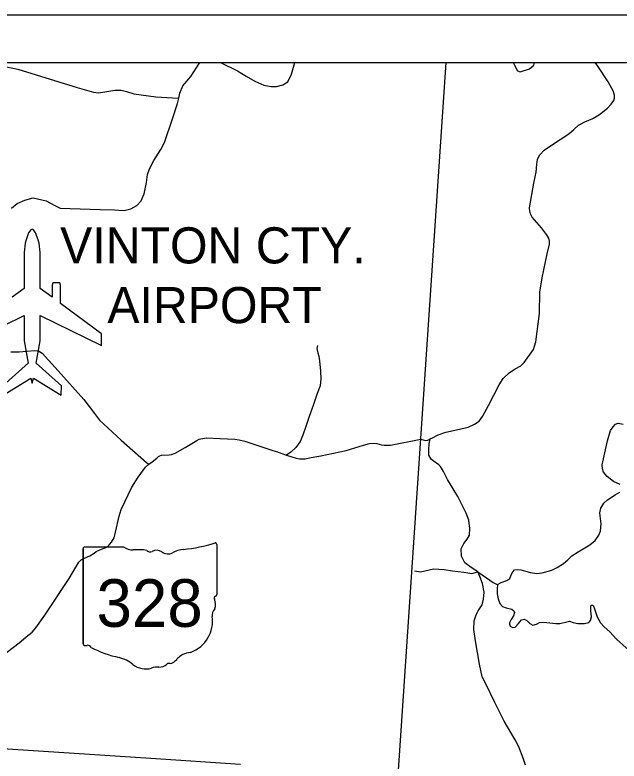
# Model space of a CAD drawing. Extents: x -22 to 431, y -18 to 160.
# Drawn here: x -17.504 to -16.235, y 27.599 to 29.164 of the extents above; entities that cross this region are included whole.
import ezdxf

# ---------------------------------------------------------------- set-up
doc = ezdxf.new("R2010")
doc.units = 0
for name, color, linetype in [('GM_X_Adjacent_County_Text', 7, 'Continuous'), ('GM_X_Airport_Location_Class_2', 7, 'Continuous'), ('GM_X_County_Road', 7, 'Continuous'), ('GM_X_County_ROW', 7, 'Continuous'), ('GM_X_Major_River_Text', 7, 'Continuous'), ('GM_X_Minor_River_Text', 7, 'Continuous'), ('GM_X_Section', 7, 'Continuous'), ('GM_X_Township_Text', 7, 'Continuous'), ('GM_X_US_Location', 7, 'Continuous')]:
    doc.layers.add(name, color=color, linetype=linetype)

msp = doc.modelspace()

# ---------------------------------------------------------------- linework, layer by layer
at = {"layer": 'GM_X_Adjacent_County_Text'}
for points in [[(-17.2858, 28.7545), (-17.2742, 28.7536), (-17.2602, 28.7571), (-17.2474, 28.7642), (-17.2388, 28.774), (-17.2321, 28.789), (-17.2277, 28.8126), (-17.2256, 28.8291), (-17.221, 28.8416), (-17.2117, 28.8586), (-17.1971, 28.8816), (-17.1899, 28.8968), (-17.1719, 28.9485), (-17.162, 28.9782), (-17.1596, 28.9898), (-17.1574, 29), (-17.1511, 29.0152), (-17.1346, 29.0351), (-17.1214, 29.0543), (-17.1155, 29.0642)], [(-17.511, 28.7585), (-17.4988, 28.7685), (-17.4829, 28.7756), (-17.4654, 28.7807), (-17.4381, 28.7742), (-17.4198, 28.7641), (-17.4086, 28.7589), (-17.3247, 28.7561), (-17.2946, 28.7552), (-17.2858, 28.7545)], [(-17.5121, 28.4571), (-17.4949, 28.4576), (-17.4629, 28.4604), (-17.454, 28.4592), (-17.4468, 28.4548), (-17.4126, 28.4177), (-17.3589, 28.3574), (-17.3365, 28.3278), (-17.3261, 28.314), (-17.2804, 28.2717), (-17.2271, 28.2252), (-17.2222, 28.2214)], [(-16.4314, 27.5899), (-16.4368, 27.6045), (-16.4456, 27.6287), (-16.4536, 27.6432), (-16.4765, 27.6825), (-16.4957, 27.7213), (-16.5146, 27.7606), (-16.5223, 27.7755), (-16.528, 27.802), (-16.5365, 27.8512), (-16.54, 27.8751), (-16.5392, 27.8929), (-16.5351, 27.9052), (-16.5312, 27.9136), (-16.5228, 27.9262), (-16.5196, 27.9385), (-16.5182, 27.9531), (-16.5222, 27.9713), (-16.5278, 27.9859), (-16.5318, 27.9957), (-16.5455, 28.0045), (-16.5591, 28.0143), (-16.5658, 28.0288), (-16.5669, 28.0442), (-16.5611, 28.0554), (-16.5544, 28.0643), (-16.5489, 28.0729), (-16.5485, 28.0869), (-16.5507, 28.104), (-16.5561, 28.1191), (-16.5736, 28.1537), (-16.5951, 28.1896), (-16.6038, 28.2062), (-16.6101, 28.2166), (-16.6136, 28.2205), (-16.6252, 28.2284), (-16.6297, 28.2318), (-16.6345, 28.2403), (-16.6344, 28.2517), (-16.634, 28.2644), (-16.6315, 28.2745)]]:
    msp.add_lwpolyline(points, dxfattribs=at)
at = {"layer": 'GM_X_Airport_Location_Class_2'}
for p, q in [((-17.08, 28.0531), (-17.08, 27.9484)), ((-17.3601, 28.0447), (-17.3601, 27.8446)), ((-17.3601, 27.8446), (-17.3601, 28.0447)), ((-17.3601, 27.8446), (-17.3601, 28.0447)), ((-17.3573, 28.0482), (-17.2753, 28.0482)), ((-17.08, 27.9485), (-17.08, 27.9484))]:
    msp.add_line(p, q, dxfattribs=at)
for centre, major_axis, start_param, end_param in [((-17.1797, 28.321), (0.2971, 0), 4.814394, 5.042369), ((-17.0831, 28.0536), (0.00312, 0), 6.141152, 7.989035), ((-17.3569, 28.0452), (0.00325, 0), 1.712693, 3.28349), ((-17.2558, 28.0714), (0.0315, 0), 4.042523, 4.731795), ((-17.2453, 27.9358), (0.113, 0), 1.404758, 1.657858), ((-17.2197, 28.0462), (0.00908, 0), 3.836095, 5.185415), ((-17.2063, 28.0231), (0.0189, 0), 0.950623, 2.079405), ((-17.182, 28.0548), (0.0227, 0), 4.081561, 5.145723), ((-17.1419, 27.9871), (0.0598, 0), 1.699011, 2.107814), ((-17.0807, 27.9408), (0.00483, 0), 1.883978, 3.671073), ((-17.0833, 27.948), (0.00334, 0), 5.05454, 6.418171), ((-17.1114, 27.9275), (0.029, 0), 5.934695, 6.695948), ((-17.0688, 27.9046), (0.0211, 0), 2.387724, 3.262537), ((-17.1631, 27.8913), (0.0743, 0), 5.101752, 6.440018), ((-17.3569, 27.8442), (0.00327, 0), 3.00124, 4.508301), ((-17.3564, 27.8646), (0.025, 0), 4.665946, 4.897461), ((-17.3513, 27.8331), (0.00901, 0), 0.519207, 1.627899), ((-17.2375, 28.0129), (0.2145, 0), 4.195997, 4.488961), ((-17.1318, 27.7884), (0.0407, 0), 1.647645, 2.488434), ((-17.3015, 27.7547), (0.0671, 0), 0.823519, 1.323587), ((-17.1806, 27.7977), (0.00639, 0), 1.147584, 2.315152), ((-17.1833, 27.8252), (0.024, 0), 4.937069, 5.64225), ((-17.2289, 27.8321), (0.0426, 0), 4.026481, 4.996735), ((-17.2043, 27.7629), (0.035, 0), 1.495662, 1.94098), ((-17.2011, 27.8171), (0.0227, 0), 4.691044, 5.507374)]:
    msp.add_ellipse(centre, major_axis=major_axis, ratio=0.941176, start_param=start_param, end_param=end_param, dxfattribs=at)
at = {"layer": 'GM_X_County_Road'}
msp.add_lwpolyline([(-16.6645, 27.9982), (-16.6522, 27.9956), (-16.6246, 28.0023), (-16.6023, 28.0008), (-16.5847, 27.9976), (-16.5614, 27.995), (-16.5442, 27.9922), (-16.5318, 27.9957)], dxfattribs=at)
at = {"layer": 'GM_X_County_ROW'}
for points in [[(-16.6315, 28.2745), (-16.6271, 28.2771), (-16.6147, 28.2832), (-16.5989, 28.2888), (-16.5828, 28.2926), (-16.5522, 28.2995), (-16.5386, 28.3055), (-16.5291, 28.3122), (-16.522, 28.3216), (-16.5096, 28.3448), (-16.4869, 28.3882), (-16.4786, 28.4011), (-16.4658, 28.4133), (-16.4532, 28.4217), (-16.4416, 28.4282), (-16.4343, 28.4352), (-16.4147, 28.4625), (-16.4124, 28.4691), (-16.4101, 28.4784), (-16.4024, 28.5375), (-16.4018, 28.5826), (-16.4004, 28.5911), (-16.3963, 28.6125), (-16.3862, 28.663), (-16.3811, 28.6831), (-16.3809, 28.6895), (-16.3823, 28.6956), (-16.3872, 28.7036), (-16.3981, 28.7178), (-16.4173, 28.7397), (-16.4212, 28.7468), (-16.4223, 28.7523), (-16.423, 28.7595), (-16.4141, 28.8114), (-16.4115, 28.8248), (-16.4095, 28.8341), (-16.4077, 28.8506), (-16.4061, 28.8614), (-16.4018, 28.8705), (-16.3923, 28.8806), (-16.3749, 28.8922), (-16.3587, 28.9027), (-16.3405, 28.9148), (-16.3298, 28.924), (-16.3201, 28.9329), (-16.3161, 28.9353), (-16.3067, 28.9401), (-16.2904, 28.9468), (-16.2759, 28.9552), (-16.2592, 28.9685), (-16.2516, 28.9772), (-16.2458, 28.9849), (-16.2445, 28.9896), (-16.2446, 28.9961), (-16.2472, 29.005), (-16.2577, 29.0237), (-16.2798, 29.0567), (-16.2854, 29.0642)], [(-17.2222, 28.2214), (-17.2155, 28.2266), (-17.2057, 28.2343), (-17.2025, 28.2375), (-17.1996, 28.2392), (-17.1956, 28.2403), (-17.1797, 28.2414), (-17.1751, 28.2422), (-17.1675, 28.2449), (-17.1461, 28.2567), (-17.1215, 28.2716), (-17.1171, 28.2739), (-17.113, 28.2751), (-17.1015, 28.2771), (-17.0727, 28.2757), (-17.0418, 28.2739), (-17.0325, 28.2725), (-17.0207, 28.2697), (-16.962, 28.2505), (-16.9523, 28.2473)], [(-16.8739, 28.2368), (-16.8617, 28.2391), (-16.8079, 28.2501), (-16.7721, 28.2614), (-16.7592, 28.2652), (-16.751, 28.2655), (-16.7438, 28.2651), (-16.7339, 28.2622), (-16.7286, 28.2612), (-16.715, 28.2618), (-16.6517, 28.2743), (-16.6416, 28.2715), (-16.637, 28.2723), (-16.6315, 28.2745)], [(-16.9523, 28.2473), (-16.9511, 28.2469), (-16.9331, 28.2407), (-16.9132, 28.2339), (-16.9058, 28.2327), (-16.8942, 28.2331), (-16.885, 28.2348), (-16.8739, 28.2368)], [(-17.4806, 27.8589), (-17.4804, 27.8591), (-17.4678, 27.8694), (-17.4599, 27.8781), (-17.4411, 27.9048), (-17.39, 27.9819), (-17.3759, 28.0055), (-17.3698, 28.0157), (-17.3646, 28.0207), (-17.3574, 28.0245), (-17.3465, 28.0291), (-17.3374, 28.0351), (-17.3328, 28.0383), (-17.3253, 28.0418), (-17.313, 28.0466), (-17.308, 28.0494), (-17.3007, 28.0583), (-17.2953, 28.0669), (-17.2924, 28.0787), (-17.2847, 28.1123), (-17.2806, 28.1267), (-17.2579, 28.1733), (-17.2452, 28.1946), (-17.234, 28.2099), (-17.2298, 28.215), (-17.2222, 28.2214)], [(-17.5596, 27.7979), (-17.5585, 27.7987), (-17.5333, 27.8171), (-17.4949, 27.8471), (-17.4806, 27.8589)]]:
    msp.add_lwpolyline(points, dxfattribs=at)
at = {"layer": 'GM_X_Major_River_Text'}
for p, q in [((-16.6991, 27.5692), (-16.5985, 29.0642)), ((-17.7289, 27.6377), (-17.218, 27.6051)), ((-17.218, 27.6051), (-17.0297, 27.5924))]:
    msp.add_line(p, q, dxfattribs=at)
at = {"layer": 'GM_X_Minor_River_Text'}
for points in [[(-17.5318, 29.0574), (-17.4974, 29.0506), (-17.3731, 29.0121), (-17.3388, 29.0019), (-17.3284, 29.0007), (-17.3106, 29.0036), (-17.2938, 29.0066), (-17.2809, 29.0065), (-17.2695, 29.0034), (-17.2538, 28.9984), (-17.2077, 28.9923), (-17.1729, 28.9899), (-17.1596, 28.9898)], [(-17.0718, 29.0642), (-17.0365, 29.0466), (-17.0179, 29.0354), (-16.9996, 29.0251), (-16.9808, 29.0165), (-16.9654, 29.014), (-16.9541, 29.0137), (-16.9409, 29.0172), (-16.9309, 29.0241), (-16.9231, 29.0402), (-16.9159, 29.0642)], [(-16.4573, 29.0642), (-16.4544, 29.0589), (-16.4483, 29.0466), (-16.4428, 29.0451), (-16.4229, 29.0508), (-16.4139, 29.0586), (-16.4127, 29.0642)], [(-16.8682, 28.4703), (-16.8695, 28.4642), (-16.8675, 28.4554), (-16.8657, 28.4485), (-16.8639, 28.4383), (-16.8619, 28.4169), (-16.8612, 28.4008), (-16.8629, 28.386), (-16.8688, 28.3697), (-16.8766, 28.3467), (-16.8858, 28.3214), (-16.8927, 28.301), (-16.8993, 28.2822), (-16.9045, 28.2693), (-16.9137, 28.2567), (-16.9242, 28.2468), (-16.9331, 28.2407)], [(-16.2326, 28.1789), (-16.2468, 28.1854), (-16.2604, 28.1959), (-16.268, 28.2048), (-16.27, 28.2118), (-16.2706, 28.2205), (-16.2595, 28.2703), (-16.2529, 28.2921), (-16.2478, 28.3003), (-16.2429, 28.3053), (-16.2367, 28.3076), (-16.2263, 28.3059)], [(-16.4906, 27.9695), (-16.4827, 27.9733), (-16.4708, 27.9777), (-16.4646, 27.9817), (-16.4619, 27.9895), (-16.4585, 27.996), (-16.4546, 27.9998), (-16.4487, 28.0004), (-16.4413, 28.0001), (-16.4208, 27.9942), (-16.4076, 27.9922), (-16.3964, 27.9934), (-16.376, 27.9995), (-16.3651, 28.0045), (-16.3517, 28.0129), (-16.3429, 28.0207), (-16.3344, 28.0293), (-16.3213, 28.0376), (-16.2968, 28.0524), (-16.2855, 28.0617), (-16.2775, 28.0728), (-16.2743, 28.0813), (-16.2724, 28.0967), (-16.2746, 28.113), (-16.2752, 28.1196), (-16.2732, 28.1293), (-16.2674, 28.1398), (-16.2596, 28.147), (-16.2432, 28.157), (-16.2338, 28.163)], [(-16.5318, 27.9957), (-16.5133, 27.9829), (-16.4996, 27.9737), (-16.4922, 27.9702), (-16.4906, 27.9695), (-16.4909, 27.9594), (-16.4912, 27.9495), (-16.4891, 27.9393), (-16.4852, 27.9291), (-16.48, 27.9229), (-16.4722, 27.9201), (-16.4601, 27.9171), (-16.4559, 27.9138), (-16.4545, 27.9102), (-16.4568, 27.9037), (-16.4618, 27.8959), (-16.4652, 27.889), (-16.4653, 27.8858), (-16.4638, 27.8815), (-16.4588, 27.8789), (-16.453, 27.8795), (-16.446, 27.8871), (-16.4398, 27.8949), (-16.4346, 27.8961), (-16.4287, 27.8937), (-16.4226, 27.8873), (-16.4161, 27.8841), (-16.4082, 27.8862), (-16.4023, 27.8893), (-16.3934, 27.8901), (-16.3679, 27.8875), (-16.3595, 27.8876), (-16.3474, 27.8903), (-16.3393, 27.8923), (-16.3313, 27.8897), (-16.3217, 27.8875), (-16.3077, 27.8872), (-16.2986, 27.8895), (-16.2948, 27.8933), (-16.293, 27.9013), (-16.2943, 27.9138), (-16.2947, 27.921), (-16.2942, 27.9244), (-16.293, 27.9256), (-16.2912, 27.9258), (-16.2898, 27.9247), (-16.2881, 27.922), (-16.2811, 27.9014), (-16.2738, 27.8891), (-16.2665, 27.8807), (-16.2545, 27.8698), (-16.2404, 27.8543), (-16.1591, 27.7819)]]:
    msp.add_lwpolyline(points, dxfattribs=at)
at = {"layer": 'GM_X_Section'}
for p, q in [((-21.9776, 29.1642), (-14.9776, 29.1642)), ((-21.8776, 29.0642), (-15.0776, 29.0642)), ((-21.8776, 29.0642), (-15.0776, 29.0642))]:
    msp.add_line(p, q, dxfattribs=at)
at = {"layer": 'GM_X_US_Location'}
for points in [[(-17.5282, 28.3663), (-17.4702, 28.4022), (-17.4676, 28.3917), (-17.4649, 28.4022), (-17.4069, 28.3663), (-17.4061, 28.3859), (-17.459, 28.4333), (-17.4505, 28.4805), (-17.4505, 28.5339), (-17.3219, 28.4705), (-17.3219, 28.4951), (-17.4083, 28.559), (-17.4083, 28.5971), (-17.4097, 28.6018), (-17.4244, 28.6018), (-17.4257, 28.5971), (-17.4257, 28.5719), (-17.4505, 28.5902), (-17.4505, 28.5902), (-17.4505, 28.6655), (-17.453, 28.6854), (-17.455, 28.6925), (-17.4602, 28.7071), (-17.4649, 28.7135), (-17.4676, 28.7146), (-17.4703, 28.7135), (-17.475, 28.7071), (-17.4801, 28.6925), (-17.4822, 28.6854), (-17.4846, 28.6655), (-17.4846, 28.5902), (-17.5094, 28.5719)], [(-17.6132, 28.4705), (-17.4846, 28.5339), (-17.4846, 28.4805), (-17.4761, 28.4333), (-17.529, 28.3859)]]:
    msp.add_lwpolyline(points, dxfattribs=at)

# ---------------------------------------------------------------- texts
at = {"layer": 'GM_X_Airport_Location_Class_2'}
msp.add_text('328', height=0.1, dxfattribs=at).set_placement((-17.3324, 27.8803))
at = {"layer": 'GM_X_Township_Text'}
for s, height, p in [('VINTON CTY.', 0.075758, (-17.4088, 28.6428)), ('AIRPORT', 0.07576, (-17.3096, 28.5175))]:
    msp.add_text(s, height=height, rotation=0, dxfattribs=at).set_placement(p)

doc.saveas('drawing.dxf')
